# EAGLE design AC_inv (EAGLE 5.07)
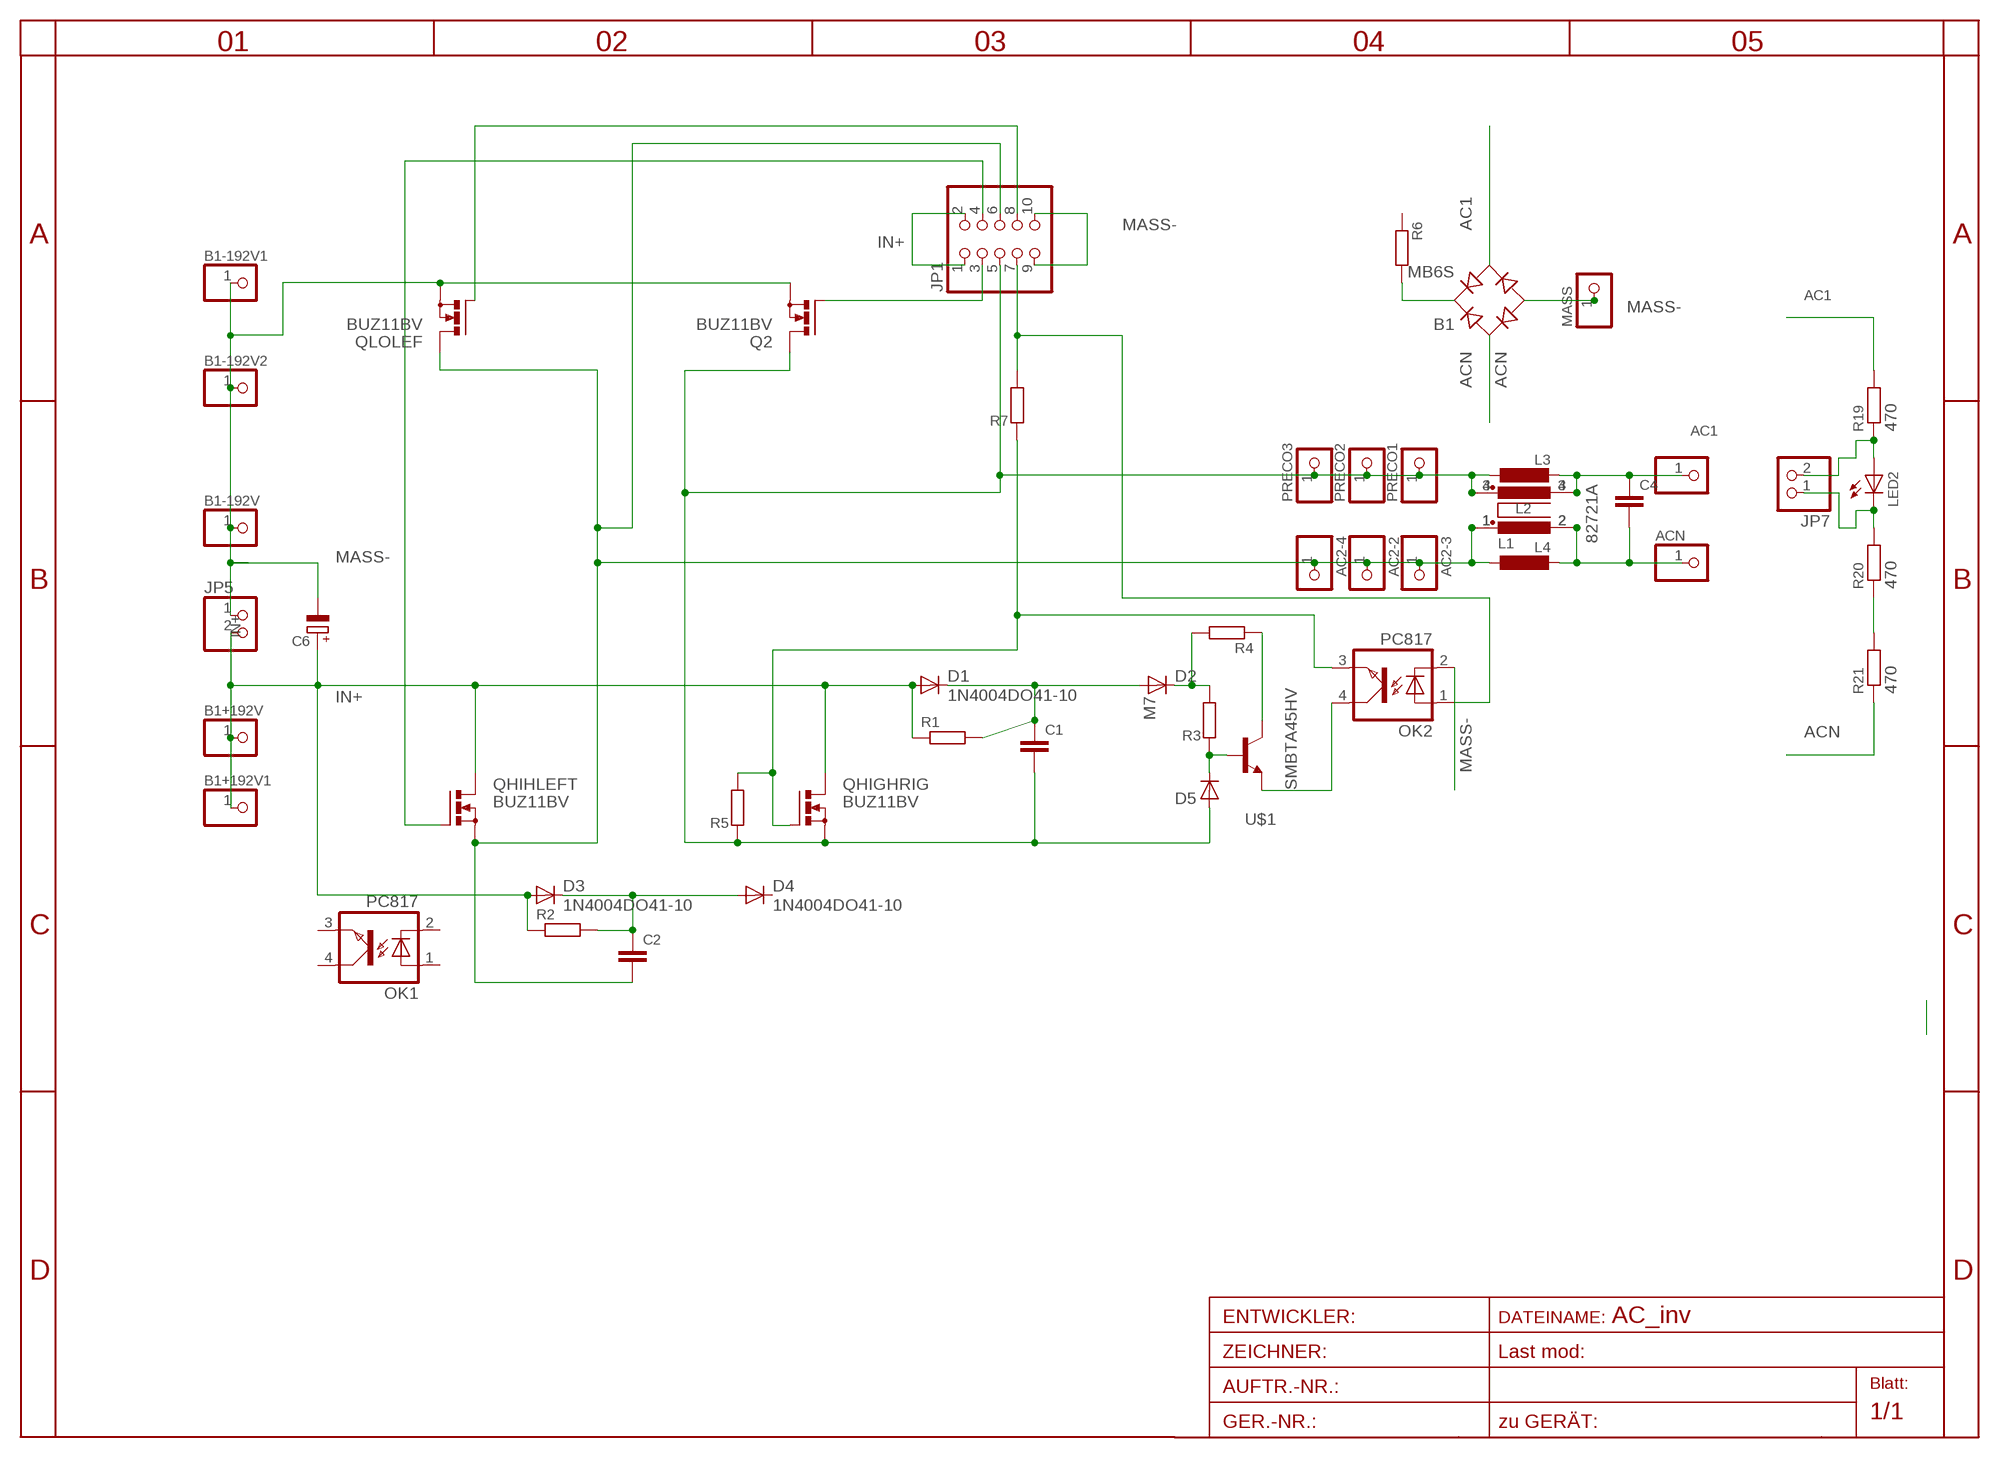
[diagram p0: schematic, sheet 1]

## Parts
AC1  PINHD-1X14.5MM  [1X4MM5]
AC2-2  PINHD-1X13MM2  [1X3MM2]
AC2-3  PINHD-1X13MM2  [1X3MM2]
AC2-4  PINHD-1X12MM3  [1X2MM3]
ACN  PINHD-1X14.5MM  [1X4MM5]
B1  MB6S  [SOIC-4]
B1+192V  PINHD-1X13MM2  [1X3MM2]
B1+192V1  PINHD-1X13MM2  [1X3MM2]
B1-192V  PINHD-1X13MM2  [1X3MM2]
B1-192V1  PINHD-1X13MM2  [1X3MM2]
B1-192V2  PINHD-1X13MM2  [1X3MM2]
C1  C-EU102-043X133  [C102-043X133]
C2  C-EU102-043X133  [C102-043X133]
C4  C-EU102-043X133  [C102-043X133]
C6  CPOL-EUE10-20  [EB20D]
D1  1N4004DO41-10  [DO41-10]
D2  M7  1N4004DO41-10  [DO41-10]
D3  1N4004DO41-10  [DO41-10]
D4  1N4004DO41-10  [DO41-10]
D5  DIODE-MINIMELF  [MINIMELF]
JP1  PINHD-2X5  [2X05]
JP5  PINHD-1X2STR  [1X02]
JP7  PINHD-1X2STR  [1X02]
L1  R1405VB1  [B1]
L2  82721A  [82721A]
L3  L-EU2200-15.24  [2200-15.24]
L4  L-EU2200-15.24  [2200-15.24]
LED2  LED3MM  [LED3MM]
MASS  PINHD-1X13MM2  [1X3MM2]
OK1  PC817  [DIL04]
OK2  PC817  [DIL04]
PRECO1  PINHD-1X12MM3  [1X2MM3]
PRECO2  PINHD-1X13MM2  [1X3MM2]
PRECO3  PINHD-1X13MM2  [1X3MM2]
Q2  BUZ11BV  [TO220BV]
QHIGHRIG  BUZ11BV  [TO220BV]
QHIHLEFT  BUZ11BV  [TO220BV]
QLOLEF  BUZ11BV  [TO220BV]
R1  R-EU_0207/10  [0207/10]
R2  R-EU_0207/10  [0207/10]
R3  R-EU_0207/40  [0207/40]
R4  R-EU_0207/50  [0207/50]
R5  R-EU_R1206  [R1206]
R6  R-EU_0207/60  [0207/60]
R7  R-EU_R1206  [R1206]
R19  470  R-EU_0204/5  [0204/5]
R20  470  R-EU_0204/2V  [0204V]
R21  470  R-EU_0204/5  [0204/5]
U$1  SMBTA45HV  [SOT23HV]

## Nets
AC1: AC1.1 B1.~2(AC2) C4.1 L1.4 L2.3 L3.2 R19.2
ACN: ACN.1 B1.~1(AC1) C4.2 L1.2 L2.2 L4.2 R21.1
BLACK: AC2-2.1 AC2-3.1 AC2-4.1 C2.2 JP1.6 L1.1 L2.1 L4.1 QHIHLEFT.S QLOLEF.D
IN+: B1+192V1.1 B1+192V.1 C6.+ D1.A D3.A JP1.1 JP1.2 JP5.2 QHIGHRIG.D QHIHLEFT.D R1.1 R2.1
MASS-: B1-192V1.1 B1-192V2.1 B1-192V.1 B1.- C6.- JP1.9 JP1.10 JP5.1 MASS.1 OK2.2(C) Q2.S QLOLEF.S
N$1: C1.1 D1.C D2.A R1.2
N$2: D2.C R3.2 R4.2
N$3: JP1.8 QLOLEF.G
N$4: JP1.4 QHIHLEFT.G
N$6: JP7.2 LED2.A R19.1
N$7: JP1.3 Q2.G
N$9: JP7.1 LED2.K(C) R20.2
N$12: C2.1 D3.C D4.A R2.2
N$13: R20.1 R21.2
N$14: R4.1 U$1.3(C)
N$15: OK2.4(COL) U$1.2(E)
N$16: D5.C R3.1 U$1.1(B)
N$17: JP1.7 OK2.1(A) R7.2
N$20: OK2.3(EMIT) QHIGHRIG.G R5.2 R7.1
N$33: B1.+ R6.2
RED: C1.2 D5.A JP1.5 L1.3 L2.4 L3.1 PRECO1.1 PRECO2.1 PRECO3.1 Q2.D QHIGHRIG.S R5.1
Unconnected: D4.C OK1.1(A) OK1.2(C) OK1.3(EMIT) OK1.4(COL) R6.1

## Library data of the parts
AC1 AC2-2-AC2-4 ACN B1+192V B1+192V1 B1-192V B1-192V1 B1-192V2 MASS PRECO1-PRECO3 = pinhead:PINHD-1X1: PIN HEADER
B1 = rectifier:MB*S: Bridge Rectifier Source: http://www.fairchildsemi.com/ds/MB/MB6S.pdf
C1 C2 C4 = rcl:C-EU: CAPACITOR, European symbol
C6 = rcl:CPOL-EU: POLARIZED CAPACITOR, European symbol
D1-D4 = diode:1N4004: DIODE
D5 = diode:DIODE-: DIODE
JP1 = pinhead:PINHD-2X5: PIN HEADER
JP5 JP7 = pinhead:PINHD-1X2: PIN HEADER
L1 = inductor-nkl:R1405V: Übertrager (verlustarm) bis typ. 400kHz Power transformer (low loss) up to typ. 400kHz
L2 = inductors:82721A: FILTER
L3 L4 = rcl:L-EU: INDUCTOR, European symbol
LED2 = led:LED: LED
OK1 OK2 = optocoupler:PC817: SHARP OPTO COUPLER
Q2 QHIGHRIG QHIHLEFT QLOLEF = transistor-power:BUZ11: N-CHANNEL MOS FET
R1-R7 R19-R21 = rcl-2:R-EU_: RESISTOR, European symbol
U$1 = transistor-npn:SMBTA45

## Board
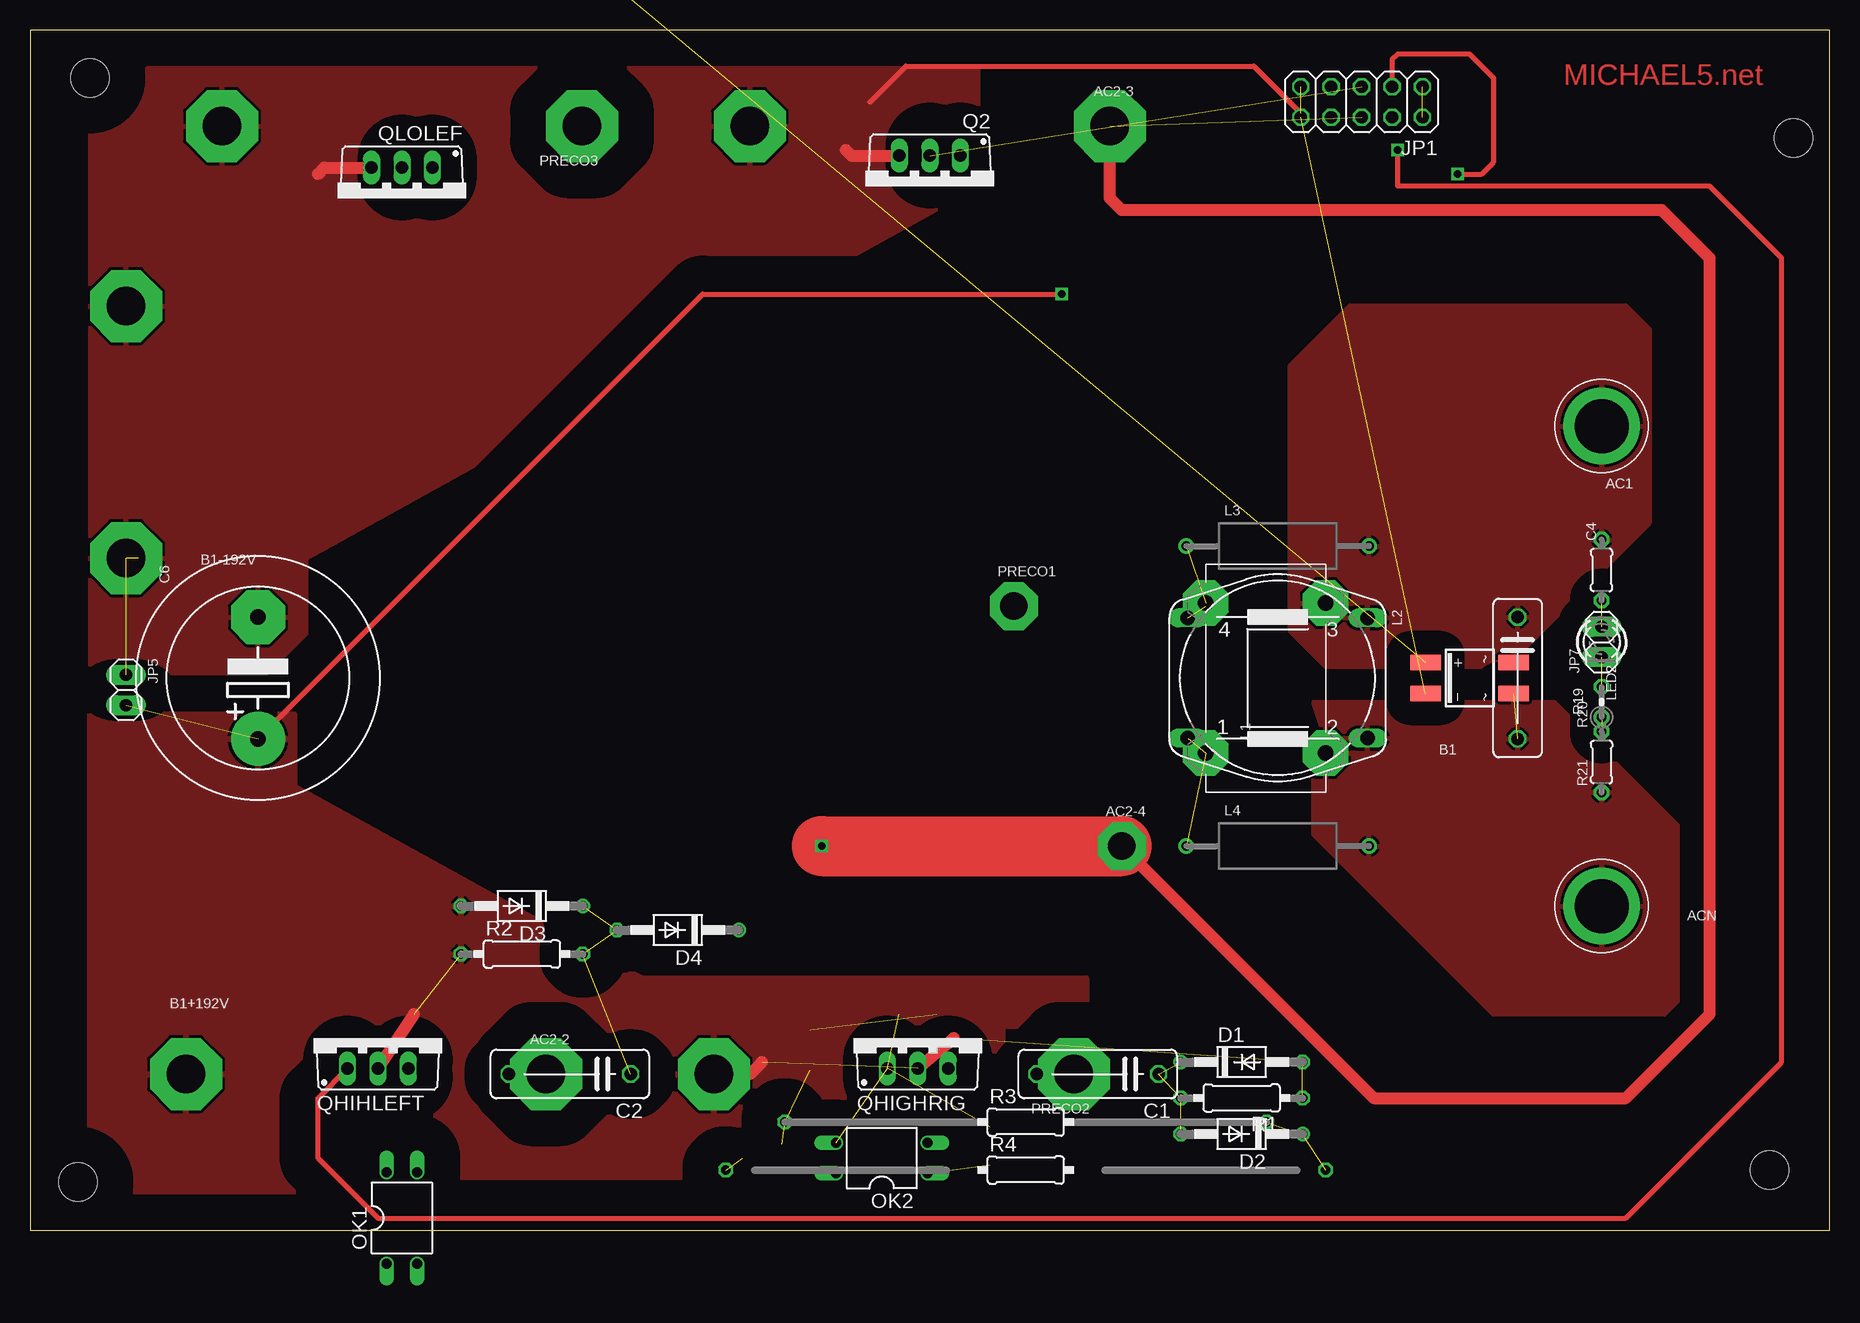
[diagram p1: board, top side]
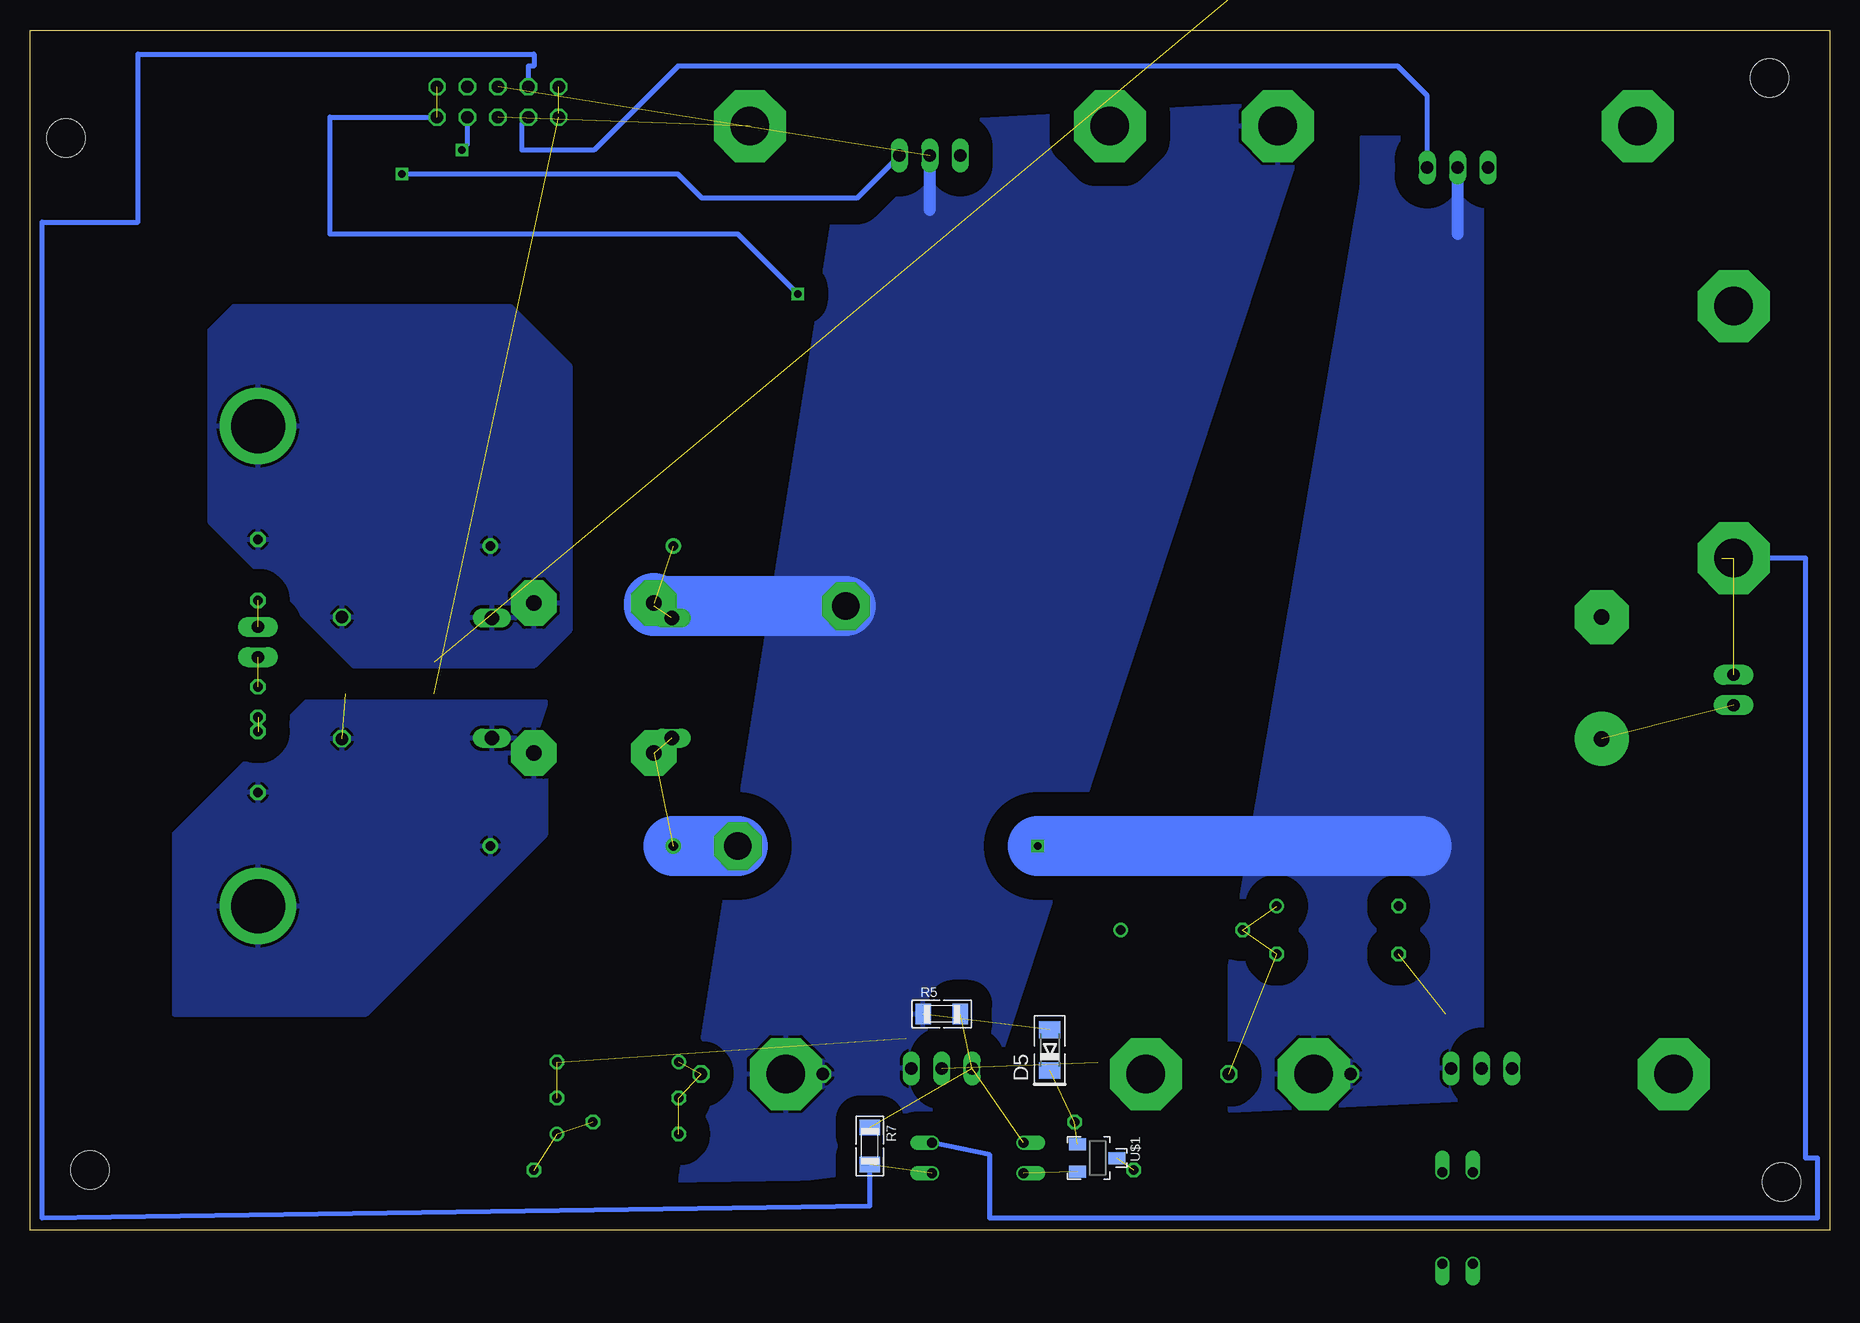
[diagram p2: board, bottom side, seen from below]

Size 150 x 100 mm. Coordinates in mm from the lower left corner, seen from the top.
Outline: 0,0 150,0 150,100 0,100 0,0
Copper layers (1*16): Top 0.035mm / dielectric 1.5mm / Bottom 0.035mm
Design rules "default *": minimum track width 12mil, minimum drill 24mil, track to track 8mil, track to pad 8mil, pad to pad 8mil, via to via 8mil, smd to smd 8mil, copper to edge 40mil, drill to drill 8mil, minimum pad ring 8mil, minimum via ring 8mil, stop-mask expansion 4mil, vias tented up to drill 0mil, thermal gap 10mil
Holes 3.2 mm at 5,96 4,4 147,91 145,5

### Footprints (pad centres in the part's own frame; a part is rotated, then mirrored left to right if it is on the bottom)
1X4MM5 = drill 4.5 pad 6.35 round: 1 0,0
1X3MM2 = drill 3.2 pad 6 octagon: 1 0,0
1X2MM3 = drill 2.3 pad 4 octagon: 1 0,0
SOIC-4 = smd 1.27 x 2.54: + 1.3,3.685; - -1.3,3.685; ~1 -1.3,-3.685; ~2 1.3,-3.685
C102-043X133 = drill 1.016 octagon: 1 -5.08,0; 2 5.08,0
EB20D = drill 1.3 pad 4.5 round: + -5.08,0 | drill 1.3 pad 4.5 octagon: - 5.08,0
DO41-10 = drill 0.8 octagon: A 5.08,0 | drill 0.8 round: C -5.08,0
MINIMELF = smd 1.4 x 1.8: A 1.7,0; C -1.7,0
2X05 = drill 1.016 octagon: 1 -5.08,-1.27; 2 -5.08,1.27; 3 -2.54,-1.27; 4 -2.54,1.27; 5 0,-1.27; 6 0,1.27; 7 2.54,-1.27; 8 2.54,1.27; 9 5.08,-1.27; 10 5.08,1.27
1X02 = drill 1.016 pad 1.676 long: 1 -1.27,0; 2 1.27,0
B1 = drill 1.27 pad 3.81 octagon: 1 -6.25,5; 2 -6.25,-5; 3 6.25,5; 4 6.25,-5
82721A = drill 1.194 long: 1 7.493,5.004; 2 -7.493,5.004; 3 -7.493,-5.004; 4 7.493,-5.004
2200-15.24 = drill 0.8 pad 1.27 round: 1 -7.62,0; 2 7.62,0
LED3MM = drill 0.8 pad 1.27 octagon: A -1.27,0; K 1.27,0
DIL04 = drill 0.813 offset: 1 -1.27,-3.81; 2 1.27,-3.81; 3 1.27,3.81; 4 -1.27,3.81
TO220BV = drill 1.016 long: D 0,-2.54; G -2.54,-2.54; S 2.54,-2.54
0207/10 = drill 0.813 octagon: 1 -5.08,0; 2 5.08,0
0207/40 = drill 0.813 octagon: 1 -20.08,0; 2 20.08,0
0207/50 = drill 0.813 octagon: 1 -25,0; 2 25,0
R1206 = smd 1.3 x 1.7: 1 -1.55,0; 2 1.55,0
0207/60 = drill 0.813 octagon: 1 -30,0; 2 30,0
0204/5 = drill 0.8 pad 1.27 octagon: 1 -2.54,0; 2 2.54,0
0204V = drill 0.8 pad 1.27 octagon: 1 -1.27,0; 2 1.27,0
SOT23HV = smd 1 x 1.4: 1 -1.15,-1.7; 2 1.15,-1.7; 3 0,1.6

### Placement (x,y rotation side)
AC1  131,67 180 top
AC2-2  43,13 0 top
AC2-3  90,92 0 top
AC2-4  91,32 0 top
ACN  131,27 180 top
B1  120,46 90 top
B1+192V  13,13 0 top
B1+192V1  57,13 0 top
B1-192V  8,56 180 top
B1-192V1  16,92 180 top
B1-192V2  60,92 0 top
C1  89,13 180 top
C2  45,13 180 top
C4  124,46 270 top
C6  19,46 90 top
D1  101,14 0 top
D2  101,8 180 top
D3  41,27 180 top
D4  54,25 180 top
D5  65,15 90 bottom
JP1  111,94 180 top
JP5  8,45 270 top
JP7  131,49 90 top
L1  103,46 90 top
L2  104,46 180 top
L3  104,57 0 top
L4  104,32 0 top
LED2  131,49 270 top
MASS  8,77 0 top
OK1  31,1 0 top
OK2  71,6 90 top
PRECO1  82,52 0 top
PRECO2  87,13 180 top
PRECO3  46,92 180 top
Q2  75,87 180 top
QHIGHRIG  74,16 0 top
QHIHLEFT  29,16 0 top
QLOLEF  31,86 180 top
R1  101,11 180 top
R2  41,23 0 top
R3  83,9 0 top
R4  83,5 0 top
R5  74,18 0 bottom
R6  not placed on the board
R7  80,7 270 bottom
R19  131,55 90 top
R20  131,44 90 top
R21  131,39 90 top
U$1  61,6 270 bottom

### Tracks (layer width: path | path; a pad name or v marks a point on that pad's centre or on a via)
AC1
  pour Bottom (isolate 2): 105,72 105,50 108,47 123,47 135,59 135,75 133,77 110,77
  pour Top (isolate 2): 105,72 105,50 108,47 123,47 135,59 135,75 133,77 110,77
ACN  (1 unrouted)
  pour Bottom (isolate 2, rank 2): 107,44 127,44 138,33 138,18 122,18 107,33 107,40 108,41
  pour Top (isolate 2, rank 2): 107,44 127,44 138,33 138,18 122,18 107,33 107,40 108,41
BLACK  (via drill 0.6)  (3 unrouted)
  Top 1: AC2-3.1 90,86 91,85 136,85 140,81 140,18 133,11 112,11 AC2-4.1
  Top 5: v66,32 AC2-4.1
  Bottom 1: 31,83 QLOLEF.D
  Bottom 5: AC2-4.1 L4.1 | 34,32 v66,32
  pour Bottom (isolate 2): 29,91 39,91 39,87 50,22 50,10 29,11
IN+  (via drill 0.6)  (6 unrouted)
  Top 0.406: v86,78 56.08,78 C6.+
  Top 1: QHIGHRIG.D 77,16 | B1+192V1.1 60,13 61,14 | QHIHLEFT.D 32,18
  Bottom 0.406: 116,92.73 JP1.2 125,92.73 125,83 116,83 91,83 v86,78
  pour Top (isolate 3): 5,43 22,43 22,37 51,21 88,21 88,17 81,17 81,3 5,3
MASS-  (4 unrouted)
  Top 0.406: JP1.10 105.92,93.08 102,97 73,97 70,94
  Top 1: QLOLEF.S 24.54,88.54 24,88 | Q2.S 68.46,89.54 68,90
  Bottom 0.406: OK2.2 70,6.27 70,1 1,1 1,6 2,6 2,56 9,56
  pour Top (isolate 3, rank 3): 5,46 23,46 23,56 79,87 79,97 10,97 5,92
N$1  (3 unrouted)
N$2  (2 unrouted)
N$3
  Bottom 0.406: QLOLEF.G 33.54,94.54 36,97 96,97 103,90 109,90 109,92.19 JP1.8
N$4  (via drill 0.6)
  Top 0.406: v114,90 114,87 140,87 146,81 146,14 133,1 29,1 24,6 24,11 QHIHLEFT.G
  Bottom 0.406: JP1.4 113.54,90.46 v114,90
N$6  (1 unrouted)
N$7  (via drill 0.6)
  Top 0.406: JP1.3 113.54,97.54 114,98 120,98 122,96 122,89 121,88 v119,88
  Bottom 0.406: v119,88 96,88 94,86 81.08,86 Q2.G
N$9  (1 unrouted)
N$12  (3 unrouted)
N$13  (1 unrouted)
N$14  (1 unrouted)
N$15  (1 unrouted)
N$16  (2 unrouted)
N$17  (1 unrouted)
  Bottom 0.406: R7.2 80,2 149,1 149,84 141,84 141,98 108,98 108,97 108.46,97 JP1.7
N$20  (3 unrouted)
N$33  (1 unrouted)
RED  (4 unrouted)
  Bottom 1: 75,85 Q2.D
  Bottom 5: PRECO1.1 98,52 L1.3
  pour Bottom (isolate 2): 43,94 80,92 80,91 82,91 96,3 72,6

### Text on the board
Top: MICHAEL5.net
